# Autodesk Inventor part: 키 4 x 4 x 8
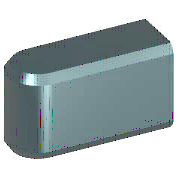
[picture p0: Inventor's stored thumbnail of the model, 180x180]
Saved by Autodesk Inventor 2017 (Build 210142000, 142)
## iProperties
Created: 2012-02
Part Number: 키 4 x 4 x 8
Material: 강철, 연강
Description: 키 및 해당 키홈
Document SubType Name: Modeling
Standard: KS B 1311
Designer: mduedu
Standards Organization: KS
Language: ko-KR
Size Designation: 4 x 4 x 8
Categories: <MemberInstance><Categories><Category DisplayName="샤프트 부품" InternalName="7f7aeb1f-a693-4053-b835-cee3144e0d98" Mnemonic="SHFT"><Category DisplayName="키" Interna
Density: 7.85 g/cm^3
Appearance: 노란색
Mass: 0.94205 g
Surface Area: 1.44138 cm^2
Volume: 0.120006 cm^3
IsCustomPart: 1
Author: mduedu
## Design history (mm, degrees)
sketch "스케치1"
  geometry: L1 (2, 2)-(8, 2); L2 (8, 2)-(8, -2); L3 (8, -2)-(2, -2); L4 (0, 7)-(0, -7) reference; L5 (-5, 0)-(30, 0) reference; A1 r 2 centre (2, 0) between (2, 2) and (2, -2)
  constraints: 6 end point, 3 tangent, 2 point on circle, 1 centre point, 1 horizontal, 1 parallel, 1 perpendicular, 1 point on line
  dimensions: "d0" = 2 radius of A1 (= 0.5 x PB); "d7" = 8 distance between parallel lines of L2 L4 (= NLG)
workplane "Work Plane1"
workplane "Work Plane2"
extrude "본체1" new body sketch "스케치1" taper "d3" = 0 deg; stored distance "d4" = 10
workaxis "Work Axis1"
workplane "Work Plane4"
body "Solid1"
chamfer "모따기1" distance "d8" = 0.25 (= PHH); stored, may be unused: second distance "d9" = 0.25 (= PHH), angle "d13" = 45 deg
other parameters: "d1" = -2.5 (= -PNT), "d2" = 1.5 (= PH - PNT), "NLG" = 8 [user parameter; used in 2 equation terms], "PB" = 4 [user parameter; used in 1 equation term], "PNT" = 2.5 [user parameter; used in 2 equation terms], "PH" = 4 [user parameter; used in 1 equation term], "PHH" = 0.25 [user parameter; used in 2 equation terms], "d10" = 0, "d16" = 0, "d17" = 0, "d18" = 0, "RR" = 0.08 [user parameter], "WDMAX" = 12 [user parameter], "PLB1" = 8 (= NLG) [user parameter], "PUEB" = 1.8 [user parameter]
